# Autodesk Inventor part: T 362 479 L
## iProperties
Company: Mayer & Müller AG Schaltgeräte
Created: 2006-01
Part Number: T 362 479 L
Material: Durethan BKV30H
Document SubType Name: Modeling
Designer: I.Baliuc
Manufacturer: Standard
Standards Organization: Custom
Description: Sockel, links
Density: 0.94 g/cm^3
Zweck: für Abdeckung LBK
Author: T.Messerschmitt
Keywords: 362242
Revision Number: 362479 L
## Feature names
1. Extrusion6
2. Bezeichnung2 [Tagging]
